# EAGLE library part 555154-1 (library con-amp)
AMP connector
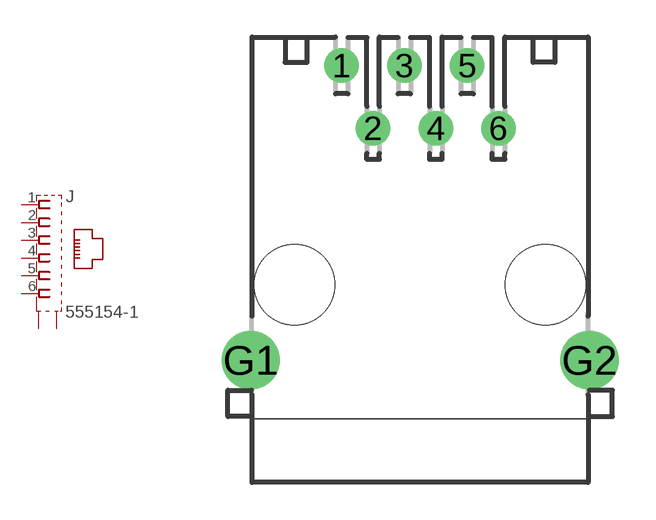
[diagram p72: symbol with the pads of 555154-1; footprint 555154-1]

Designator prefix J

## 555154-1 (MF: TYCO ELECTRONICS; MPN: 5555154-1; OC_FARNELL: 1214657; OC_NEWARK: 42K8757)  [555154-1]
1  1  pas
2  2  pas
3  3  pas
4  4  pas
5  5  pas
6  6  pas
G1  S1  pas
G2  S2  pas

## Footprint 555154-1 (pad centres in mm)
Modular Jack PC Board Ground
drill 0.889 round: 1 -3.175,8.89; 2 -1.905,6.35; 3 -0.635,8.89; 4 0.635,6.35; 5 1.905,8.89; 6 3.175,6.35
drill 1.575 pad 2.184 round: G1 -6.858,-3.048; G2 6.858,-3.048
hole 3.251 at -5.08,0
hole 3.251 at 5.08,0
